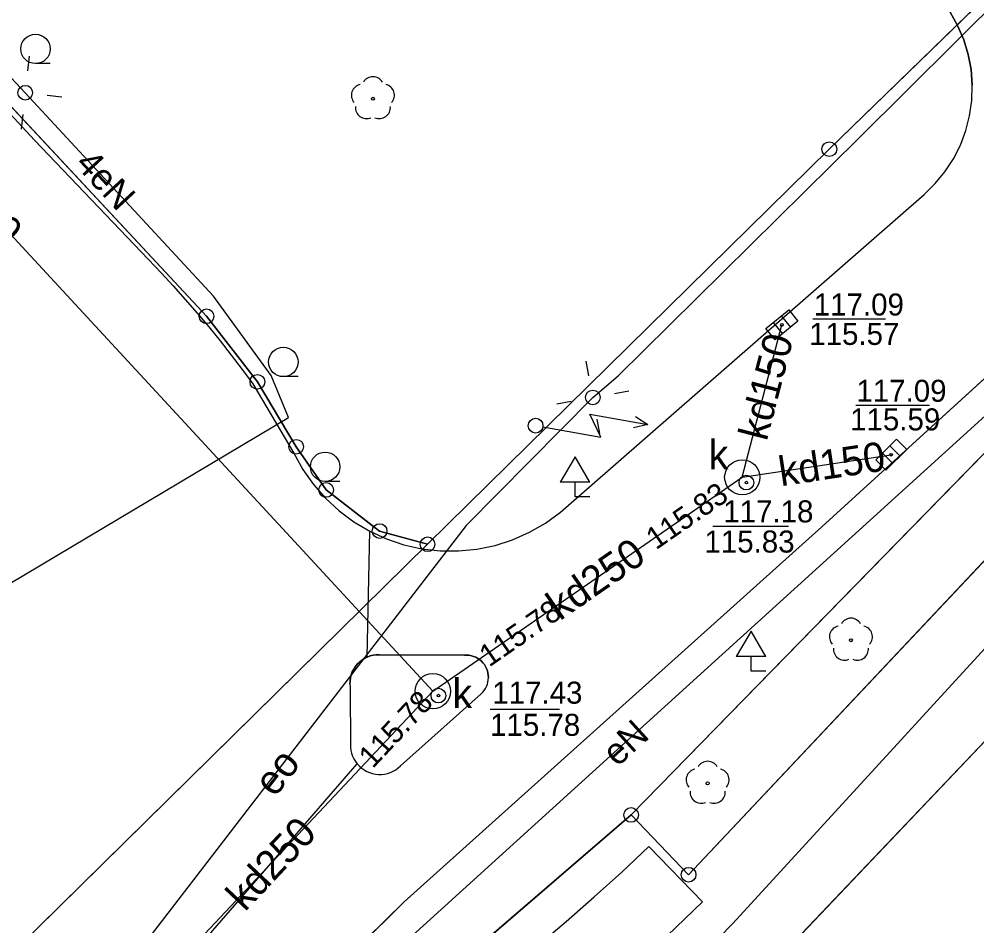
# Model space of a CAD drawing. Extents: x 6434771 to 6436222, y 5663454 to 5664782.
# Drawn here: x 6435500.32 to 6435532.91, y 5663768.81 to 5663799.67 of the extents above; entities that cross this region are included whole.
import ezdxf

# ---------------------------------------------------------------- set-up
doc = ezdxf.new("R2010")
doc.units = 0
for name, color, linetype in [('Warstwa 1', 7, 'Continuous'), ('Warstwa 10', 7, 'Continuous'), ('Warstwa 11', 7, 'Continuous'), ('Warstwa 12', 7, 'Continuous'), ('Warstwa 13', 7, 'Continuous'), ('Warstwa 14', 7, 'Continuous'), ('Warstwa 15', 7, 'Continuous'), ('Warstwa 2', 7, 'Continuous'), ('Warstwa 31', 7, 'Continuous'), ('Warstwa 37', 7, 'Continuous'), ('Warstwa 4', 7, 'Continuous'), ('Warstwa 40', 7, 'Continuous'), ('Warstwa 5', 7, 'Continuous'), ('Warstwa 6', 7, 'Continuous'), ('Warstwa 7', 7, 'Continuous'), ('Warstwa 8', 7, 'Continuous'), ('Warstwa 9', 7, 'Continuous')]:
    doc.layers.add(name, color=color, linetype=linetype)

msp = doc.modelspace()

# ---------------------------------------------------------------- linework, layer by layer
at = {"layer": 'Warstwa 1'}
for p, q in [((6435527.892, 5663795.248), (6435570.992, 5663837.121)), ((6435527.892, 5663795.248), (6435570.992, 5663837.121)), ((6435521.147, 5663772.588), (6435548.671, 5663800.788)), ((6435521.147, 5663772.588), (6435548.671, 5663800.788)), ((6435497.48, 5663799.45), (6435506.7, 5663789.56)), ((6435497.48, 5663799.45), (6435506.7, 5663789.56)), ((6435514.22, 5663781.8), (6435527.892, 5663795.248)), ((6435514.22, 5663781.8), (6435527.892, 5663795.248)), ((6435523.103, 5663770.554), (6435543.163, 5663791.864)), ((6435523.103, 5663770.554), (6435543.163, 5663791.864)), ((6435506.7, 5663789.56), (6435508.43, 5663787.33)), ((6435506.7, 5663789.56), (6435508.43, 5663787.33)), ((6435526.058, 5663767.608), (6435546.338, 5663788.935)), ((6435526.058, 5663767.608), (6435546.338, 5663788.935)), ((6435508.43, 5663787.33), (6435509.75, 5663785.12)), ((6435508.43, 5663787.33), (6435509.75, 5663785.12)), ((6435509.75, 5663785.12), (6435510.77, 5663783.65)), ((6435509.75, 5663785.12), (6435510.77, 5663783.65)), ((6435510.77, 5663783.65), (6435512.59, 5663782.25)), ((6435510.77, 5663783.65), (6435512.59, 5663782.25)), ((6435512.59, 5663782.25), (6435514.22, 5663781.8)), ((6435512.59, 5663782.25), (6435514.22, 5663781.8)), ((6435492.76, 5663760.678), (6435514.22, 5663781.8)), ((6435492.76, 5663760.678), (6435514.22, 5663781.8)), ((6435509.313, 5663762.399), (6435521.147, 5663772.588)), ((6435509.313, 5663762.399), (6435521.147, 5663772.588)), ((6435521.147, 5663772.588), (6435523.103, 5663770.554)), ((6435521.147, 5663772.588), (6435523.103, 5663770.554))]:
    msp.add_line(p, q, dxfattribs=at)
msp.add_circle((6435517.897, 5663785.838), 0.25, dxfattribs=at)
at = {"layer": 'Warstwa 10'}
for centre in [(6435527.892, 5663795.248), (6435506.7, 5663789.56), (6435508.43, 5663787.33), (6435509.75, 5663785.12), (6435510.77, 5663783.65), (6435512.59, 5663782.25), (6435514.22, 5663781.8), (6435521.147, 5663772.588), (6435523.103, 5663770.554)]:
    msp.add_circle(centre, 0.25, dxfattribs=at)
at = {"layer": 'Warstwa 11'}
for centre in [(6435512.361, 5663796.966), (6435528.628, 5663778.535), (6435523.752, 5663773.664)]:
    msp.add_circle(centre, 0.05, dxfattribs=at)
for centre, start, end in [((6435512.361, 5663797.341), 30.1471, 149.8529), ((6435512.004, 5663797.082), 102.1471, 221.8529), ((6435512.718, 5663797.082), 318.1471, 77.8529), ((6435512.141, 5663796.663), 174.1471, 293.8529), ((6435512.581, 5663796.663), 246.1471, 5.8529), ((6435528.628, 5663778.91), 30.1471, 149.8529), ((6435528.271, 5663778.651), 102.1471, 221.8529), ((6435528.985, 5663778.651), 318.1471, 77.8529), ((6435528.408, 5663778.232), 174.1471, 293.8529), ((6435528.848, 5663778.232), 246.1471, 5.8529), ((6435523.395, 5663773.78), 102.1471, 221.8529), ((6435523.752, 5663774.039), 30.1471, 149.8529), ((6435524.109, 5663773.78), 318.1471, 77.8529), ((6435523.532, 5663773.361), 174.1471, 293.8529), ((6435523.972, 5663773.361), 246.1471, 5.8529)]:
    msp.add_arc(centre, 0.375, start, end, dxfattribs=at)
at = {"layer": 'Warstwa 12'}
for points in [[(6435497.61, 5663776.71), (6435497.62, 5663777.21), (6435497.63, 5663777.61), (6435498.65, 5663778.12), (6435498.93, 5663779.83), (6435509.49, 5663786.12), (6435508.9, 5663787.55), (6435506.94, 5663790.25), (6435500.53, 5663797.17), (6435496.25, 5663801.75), (6435493.32, 5663804.59), (6435490.84, 5663808.57), (6435490.34, 5663810.94), (6435482.363, 5663815.454)], [(6435519.85, 5663786.8), (6435520.711, 5663787.533), (6435522.45, 5663789.259), (6435528.881, 5663795.616), (6435533.856, 5663800.554)], [(6435506.84, 5663759.48), (6435507.02, 5663760.06), (6435509.66, 5663764.81), (6435538.22, 5663790.73)], [(6435519.85, 5663786.8), (6435515.54, 5663782.44), (6435503.04, 5663766.2), (6435502.06, 5663764.42), (6435502.22, 5663763.12), (6435502.29, 5663762.51), (6435501.16, 5663760.21), (6435500.55, 5663759.21), (6435505.86, 5663755.16), (6435506.73, 5663754.16), (6435505.81, 5663752.14)]]:
    msp.add_lwpolyline(points, dxfattribs=at)
at = {"layer": 'Warstwa 14'}
for p, q in [((6435529.808, 5663789.467), (6435527.334, 5663789.467)), ((6435531.303, 5663786.53), (6435528.793, 5663786.53)), ((6435526.498, 5663782.411), (6435523.929, 5663782.411)), ((6435518.715, 5663776.174), (6435516.347, 5663776.174))]:
    msp.add_line(p, q, dxfattribs=at)
for centre in [(6435526.28, 5663789.27), (6435530, 5663784.85), (6435525.07, 5663783.9), (6435525.07, 5663783.9), (6435514.59, 5663776.65), (6435514.59, 5663776.65), (6435514.59, 5663776.65)]:
    msp.add_circle(centre, 0.045, dxfattribs=at)
at = {"layer": 'Warstwa 15'}
for centre in [(6435524.93, 5663784.08), (6435514.4, 5663776.8)]:
    msp.add_circle(centre, 0.6, dxfattribs=at)
at = {"layer": 'Warstwa 2'}
for centre in [(6435500.53, 5663797.17), (6435519.845, 5663786.799)]:
    msp.add_circle(centre, 0.25, dxfattribs=at)
at = {"layer": 'Warstwa 31'}
for p, q in [((6435519.738, 5663783.911), (6435519.238, 5663784.777)), ((6435519.238, 5663783.411), (6435519.238, 5663783.911)), ((6435519.738, 5663783.411), (6435519.238, 5663783.411)), ((6435525.727, 5663777.979), (6435525.227, 5663778.845)), ((6435525.227, 5663777.479), (6435525.227, 5663777.979)), ((6435525.727, 5663777.479), (6435525.227, 5663777.479))]:
    msp.add_line(p, q, dxfattribs=at)
for points in [[(6435519.238, 5663784.777), (6435518.738, 5663783.911)], [(6435519.738, 5663783.911), (6435518.738, 5663783.911)], [(6435525.227, 5663778.845), (6435524.727, 5663777.979)], [(6435525.727, 5663777.979), (6435524.727, 5663777.979)]]:
    msp.add_lwpolyline(points, dxfattribs=at)
at = {"layer": 'Warstwa 37'}
for points in [[(6435536.411, 5663781.778), (6435524.604, 5663768.893)], [(6435524.604, 5663768.893), (6435523.66, 5663767.922), (6435522.692, 5663766.975), (6435521.701, 5663766.052), (6435520.687, 5663765.154), (6435519.652, 5663764.282), (6435518.595, 5663763.435), (6435517.517, 5663762.615), (6435516.419, 5663761.822), (6435515.302, 5663761.056)]]:
    msp.add_lwpolyline(points, dxfattribs=at)
at = {"layer": 'Warstwa 4'}
for p, q in [((6435526.257, 5663789.574), (6435526.574, 5663789.187)), ((6435525.986, 5663789.353), (6435526.303, 5663788.966)), ((6435529.7, 5663784.905), (6435530.051, 5663784.549)), ((6435529.949, 5663785.151), (6435530.3, 5663784.795))]:
    msp.add_line(p, q, dxfattribs=at)
for points in [[(6435500.615, 5663797.915), (6435500.671, 5663798.412)], [(6435501.275, 5663797.085), (6435501.772, 5663797.029)], [(6435500.445, 5663796.425), (6435500.389, 5663795.928)], [(6435519.71, 5663787.537), (6435519.619, 5663788.028)], [(6435520.583, 5663786.934), (6435521.074, 5663787.025)], [(6435519.107, 5663786.664), (6435518.616, 5663786.573)], [(6435519.98, 5663786.061), (6435520.071, 5663785.57)]]:
    msp.add_lwpolyline(points, dxfattribs=at)
for points in [[(6435525.735, 5663789.147), (6435526.509, 5663789.78), (6435526.825, 5663789.393), (6435526.051, 5663788.76)], [(6435529.469, 5663784.676), (6435530.18, 5663785.379), (6435530.531, 5663785.024), (6435529.82, 5663784.321)]]:
    msp.add_lwpolyline(points, close=True, dxfattribs=at)
for centre in [(6435525.07, 5663783.9), (6435514.59, 5663776.65)]:
    msp.add_circle(centre, 0.25, dxfattribs=at)
at = {"layer": 'Warstwa 40'}
msp.add_line((6435518.143, 5663785.795), (6435520.113, 5663785.451), dxfattribs=at)
for points in [[(6435518.143, 5663785.795), (6435520.113, 5663785.451), (6435519.741, 5663786.227), (6435521.712, 5663785.883)], [(6435521.292, 5663786.155), (6435521.712, 5663785.883), (6435521.225, 5663785.769)]]:
    msp.add_lwpolyline(points, dxfattribs=at)
msp.add_circle((6435517.897, 5663785.838), 0.25, dxfattribs=at)
at = {"layer": 'Warstwa 6'}
for p, q in [((6435501.38, 5663798.16), (6435500.88, 5663798.16)), ((6435509.813, 5663787.506), (6435509.313, 5663787.506)), ((6435511.236, 5663783.938), (6435510.736, 5663783.938))]:
    msp.add_line(p, q, dxfattribs=at)
for points in [[(6435497.48, 5663799.45), (6435506.7, 5663789.56), (6435508.43, 5663787.33), (6435509.75, 5663785.12), (6435510.77, 5663783.65), (6435512.59, 5663782.25), (6435514.22, 5663781.8), (6435527.892, 5663795.248), (6435570.992, 5663837.121), (6435586.939, 5663852.54), (6435599.429, 5663860.81), (6435608.979, 5663864.176), (6435617.268, 5663864.926), (6435627.619, 5663865.031), (6435640.832, 5663867.732), (6435649.164, 5663870.462), (6435662.228, 5663877.475)], [(6435570.992, 5663837.121), (6435527.892, 5663795.248), (6435514.22, 5663781.8), (6435492.76, 5663760.678), (6435502.002, 5663754.167), (6435504.911, 5663757.372), (6435509.313, 5663762.399), (6435521.147, 5663772.588), (6435548.671, 5663800.788)], [(6435548.671, 5663800.788), (6435521.147, 5663772.588), (6435523.103, 5663770.554), (6435543.163, 5663791.864), (6435547.892, 5663795.057), (6435552.721, 5663796.629), (6435556.818, 5663797.2), (6435563.282, 5663796.602), (6435571.928, 5663792.927), (6435578.259, 5663786.341), (6435582.013, 5663777.505), (6435581.903, 5663767.556), (6435577.311, 5663758.31), (6435571.527, 5663753.09), (6435533.459, 5663736.247), (6435548.335, 5663741.528), (6435569.265, 5663749.587), (6435586.612, 5663753.338), (6435592.395, 5663758.549), (6435606.056, 5663770.975), (6435613.539, 5663781.965), (6435615.412, 5663784.713), (6435621.643, 5663793.868), (6435632.116, 5663809.073)], [(6435547.198, 5663801.229), (6435542.95, 5663796.915), (6435539.74, 5663793.64), (6435534.45, 5663788.61), (6435527.64, 5663782.4), (6435513.43, 5663769.63), (6435509.63, 5663765.9)], [(6435531.12, 5663793.71), (6435531.495, 5663794.077), (6435531.828, 5663794.482), (6435532.114, 5663794.921), (6435532.351, 5663795.389), (6435532.536, 5663795.88), (6435532.666, 5663796.388), (6435532.739, 5663796.907), (6435532.756, 5663797.432), (6435532.715, 5663797.955), (6435532.618, 5663798.47), (6435532.465, 5663798.972), (6435532.258, 5663799.453), (6435532, 5663799.91)], [(6435492.76, 5663760.678), (6435514.22, 5663781.8), (6435512.59, 5663782.25), (6435510.77, 5663783.65), (6435509.75, 5663785.12), (6435508.43, 5663787.33), (6435506.7, 5663789.56), (6435497.48, 5663799.45)], [(6435497.34, 5663799.33), (6435500.85, 5663795.55), (6435504.73, 5663791.49), (6435505.152, 5663791.044), (6435505.568, 5663790.592), (6435505.977, 5663790.134), (6435506.379, 5663789.67), (6435506.774, 5663789.2), (6435507.161, 5663788.723), (6435507.541, 5663788.241), (6435507.914, 5663787.753), (6435508.28, 5663787.26), (6435509.67, 5663784.9), (6435509.974, 5663784.352), (6435510.335, 5663783.838), (6435510.748, 5663783.366), (6435511.208, 5663782.94), (6435511.711, 5663782.565), (6435512.251, 5663782.245), (6435512.821, 5663781.983), (6435513.416, 5663781.784), (6435514.028, 5663781.648), (6435514.652, 5663781.578), (6435515.279, 5663781.573), (6435515.903, 5663781.636), (6435516.517, 5663781.763), (6435517.115, 5663781.955), (6435517.689, 5663782.209), (6435518.232, 5663782.522), (6435518.74, 5663782.89), (6435531.12, 5663793.71)], [(6435552.721, 5663796.629), (6435547.892, 5663795.057), (6435543.163, 5663791.864), (6435523.103, 5663770.554), (6435521.147, 5663772.588), (6435509.313, 5663762.399), (6435504.911, 5663757.372), (6435502.002, 5663754.167), (6435506.094, 5663751.807), (6435526.058, 5663767.608), (6435546.338, 5663788.935), (6435550.407, 5663791.326)], [(6435511.59, 5663776.94), (6435511.6, 5663774.89), (6435511.613, 5663774.788), (6435511.637, 5663774.687), (6435511.671, 5663774.589), (6435511.715, 5663774.496), (6435511.768, 5663774.407), (6435511.831, 5663774.325), (6435511.901, 5663774.249), (6435511.979, 5663774.181), (6435512.063, 5663774.122), (6435512.153, 5663774.072), (6435512.248, 5663774.031), (6435512.347, 5663774), (6435512.448, 5663773.979), (6435512.551, 5663773.969), (6435512.654, 5663773.97), (6435512.757, 5663773.982), (6435512.858, 5663774.004), (6435512.956, 5663774.036), (6435513.05, 5663774.078), (6435513.14, 5663774.13), (6435513.223, 5663774.191), (6435513.3, 5663774.26), (6435516.05, 5663776.71), (6435516.104, 5663776.766), (6435516.152, 5663776.827), (6435516.194, 5663776.893), (6435516.229, 5663776.963), (6435516.256, 5663777.036), (6435516.276, 5663777.112), (6435516.288, 5663777.189), (6435516.292, 5663777.267), (6435516.288, 5663777.345), (6435516.277, 5663777.422), (6435516.257, 5663777.498), (6435516.23, 5663777.571), (6435516.195, 5663777.641), (6435516.154, 5663777.707), (6435516.106, 5663777.768), (6435516.052, 5663777.824), (6435515.992, 5663777.875), (6435515.928, 5663777.919), (6435515.859, 5663777.956), (6435515.787, 5663777.987), (6435515.712, 5663778.009), (6435515.636, 5663778.024), (6435515.558, 5663778.031), (6435515.48, 5663778.03), (6435512.58, 5663778.04), (6435512.475, 5663778.038), (6435512.371, 5663778.024), (6435512.268, 5663777.999), (6435512.17, 5663777.963), (6435512.075, 5663777.916), (6435511.986, 5663777.86), (6435511.904, 5663777.794), (6435511.83, 5663777.72), (6435511.764, 5663777.638), (6435511.707, 5663777.549), (6435511.66, 5663777.455), (6435511.624, 5663777.356), (6435511.598, 5663777.254), (6435511.584, 5663777.15), (6435511.581, 5663777.045), (6435511.59, 5663776.94)]]:
    msp.add_lwpolyline(points, dxfattribs=at)
msp.add_lwpolyline([(6435557.506, 5663792.861), (6435553.992, 5663792.563), (6435550.407, 5663791.326), (6435546.338, 5663788.935), (6435526.058, 5663767.608), (6435506.094, 5663751.807), (6435529.689, 5663738.733), (6435568.207, 5663755.62), (6435573.888, 5663760.552), (6435577.803, 5663768.465), (6435578.155, 5663776.031), (6435574.677, 5663783.684), (6435569.533, 5663789.156), (6435561.733, 5663792.55)], close=True, dxfattribs=at)
for centre, radius in [((6435500.88, 5663798.66), 0.5), ((6435526.28, 5663789.27), 0.045), ((6435509.313, 5663788.006), 0.5), ((6435510.736, 5663784.438), 0.5), ((6435530, 5663784.85), 0.045), ((6435525.07, 5663783.9), 0.045), ((6435514.59, 5663776.65), 0.045)]:
    msp.add_circle(centre, radius, dxfattribs=at)
at = {"layer": 'Warstwa 7'}
for points in [[(6435482.98, 5663810.8), (6435514.4, 5663776.8)], [(6435524.93, 5663784.08), (6435526.28, 5663789.27)], [(6435524.93, 5663784.08), (6435530, 5663784.85)], [(6435514.4, 5663776.8), (6435524.93, 5663784.08)], [(6435514.4, 5663776.8), (6435502.93, 5663764.6)]]:
    msp.add_lwpolyline(points, dxfattribs=at)
at = {"layer": 'Warstwa 8'}
for p, q in [((6435532, 5663799.91), (6435532.258, 5663799.453)), ((6435497.357, 5663799.312), (6435500.85, 5663795.55)), ((6435532.258, 5663799.453), (6435532.465, 5663798.972)), ((6435532.465, 5663798.972), (6435532.618, 5663798.47)), ((6435532.618, 5663798.47), (6435532.715, 5663797.955)), ((6435532.715, 5663797.955), (6435532.756, 5663797.432)), ((6435532.739, 5663796.907), (6435532.756, 5663797.432)), ((6435532.666, 5663796.388), (6435532.739, 5663796.907)), ((6435532.536, 5663795.88), (6435532.666, 5663796.388)), ((6435532.351, 5663795.389), (6435532.536, 5663795.88)), ((6435500.85, 5663795.55), (6435504.73, 5663791.49)), ((6435532.114, 5663794.921), (6435532.351, 5663795.389)), ((6435531.828, 5663794.482), (6435532.114, 5663794.921)), ((6435531.495, 5663794.077), (6435531.828, 5663794.482)), ((6435531.12, 5663793.71), (6435531.495, 5663794.077)), ((6435518.74, 5663782.89), (6435531.12, 5663793.71)), ((6435504.73, 5663791.49), (6435505.152, 5663791.044)), ((6435505.152, 5663791.044), (6435505.568, 5663790.592)), ((6435505.568, 5663790.592), (6435505.977, 5663790.134)), ((6435505.977, 5663790.134), (6435506.379, 5663789.67)), ((6435506.379, 5663789.67), (6435506.774, 5663789.2)), ((6435506.774, 5663789.2), (6435507.161, 5663788.723)), ((6435507.161, 5663788.723), (6435507.541, 5663788.241)), ((6435527.64, 5663782.4), (6435534.45, 5663788.61)), ((6435507.541, 5663788.241), (6435507.914, 5663787.753)), ((6435507.914, 5663787.753), (6435508.28, 5663787.26)), ((6435508.28, 5663787.26), (6435509.67, 5663784.9)), ((6435509.67, 5663784.9), (6435509.974, 5663784.352)), ((6435509.974, 5663784.352), (6435510.335, 5663783.838)), ((6435510.335, 5663783.838), (6435510.748, 5663783.366)), ((6435510.748, 5663783.366), (6435511.208, 5663782.94)), ((6435511.208, 5663782.94), (6435511.711, 5663782.565)), ((6435518.232, 5663782.522), (6435518.74, 5663782.89)), ((6435511.711, 5663782.565), (6435512.251, 5663782.245)), ((6435513.43, 5663769.63), (6435527.64, 5663782.4)), ((6435517.689, 5663782.209), (6435518.232, 5663782.522)), ((6435512.17, 5663777.963), (6435512.251, 5663782.245)), ((6435512.17, 5663777.963), (6435512.251, 5663782.245)), ((6435512.251, 5663782.245), (6435512.821, 5663781.983)), ((6435512.821, 5663781.983), (6435513.416, 5663781.784)), ((6435517.115, 5663781.955), (6435517.689, 5663782.209)), ((6435513.416, 5663781.784), (6435514.028, 5663781.648)), ((6435514.028, 5663781.648), (6435514.652, 5663781.578)), ((6435515.279, 5663781.573), (6435515.903, 5663781.636)), ((6435515.903, 5663781.636), (6435516.517, 5663781.763)), ((6435516.517, 5663781.763), (6435517.115, 5663781.955)), ((6435514.652, 5663781.578), (6435515.279, 5663781.573)), ((6435511.83, 5663777.72), (6435511.904, 5663777.794)), ((6435511.904, 5663777.794), (6435511.986, 5663777.86)), ((6435511.986, 5663777.86), (6435512.075, 5663777.916)), ((6435512.075, 5663777.916), (6435512.17, 5663777.963)), ((6435512.17, 5663777.963), (6435512.268, 5663777.999)), ((6435512.268, 5663777.999), (6435512.371, 5663778.024)), ((6435512.371, 5663778.024), (6435512.475, 5663778.038)), ((6435512.475, 5663778.038), (6435512.58, 5663778.04)), ((6435512.58, 5663778.04), (6435515.48, 5663778.03)), ((6435515.48, 5663778.03), (6435515.558, 5663778.031)), ((6435515.558, 5663778.031), (6435515.636, 5663778.024)), ((6435515.636, 5663778.024), (6435515.712, 5663778.009)), ((6435515.712, 5663778.009), (6435515.787, 5663777.987)), ((6435515.787, 5663777.987), (6435515.859, 5663777.956)), ((6435515.859, 5663777.956), (6435515.928, 5663777.919)), ((6435515.928, 5663777.919), (6435515.992, 5663777.875)), ((6435515.992, 5663777.875), (6435516.052, 5663777.824)), ((6435516.052, 5663777.824), (6435516.106, 5663777.768)), ((6435516.106, 5663777.768), (6435516.154, 5663777.707)), ((6435511.624, 5663777.356), (6435511.66, 5663777.455)), ((6435511.66, 5663777.455), (6435511.707, 5663777.549)), ((6435511.707, 5663777.549), (6435511.764, 5663777.638)), ((6435511.764, 5663777.638), (6435511.83, 5663777.72)), ((6435516.154, 5663777.707), (6435516.195, 5663777.641)), ((6435516.195, 5663777.641), (6435516.23, 5663777.571)), ((6435516.23, 5663777.571), (6435516.257, 5663777.498)), ((6435516.257, 5663777.498), (6435516.277, 5663777.422)), ((6435516.277, 5663777.422), (6435516.288, 5663777.345)), ((6435511.581, 5663777.045), (6435511.584, 5663777.15)), ((6435511.584, 5663777.15), (6435511.598, 5663777.254)), ((6435511.598, 5663777.254), (6435511.624, 5663777.356)), ((6435516.256, 5663777.036), (6435516.276, 5663777.112)), ((6435516.276, 5663777.112), (6435516.288, 5663777.189)), ((6435516.288, 5663777.345), (6435516.292, 5663777.267)), ((6435516.288, 5663777.189), (6435516.292, 5663777.267)), ((6435511.581, 5663777.045), (6435511.59, 5663776.94)), ((6435511.59, 5663776.94), (6435511.6, 5663774.89)), ((6435516.05, 5663776.71), (6435516.104, 5663776.766)), ((6435516.104, 5663776.766), (6435516.152, 5663776.827)), ((6435516.152, 5663776.827), (6435516.194, 5663776.893)), ((6435516.194, 5663776.893), (6435516.229, 5663776.963)), ((6435516.229, 5663776.963), (6435516.256, 5663777.036)), ((6435513.3, 5663774.26), (6435516.05, 5663776.71)), ((6435511.6, 5663774.89), (6435511.613, 5663774.788)), ((6435511.613, 5663774.788), (6435511.637, 5663774.687)), ((6435511.637, 5663774.687), (6435511.671, 5663774.589)), ((6435511.671, 5663774.589), (6435511.715, 5663774.496)), ((6435511.715, 5663774.496), (6435511.768, 5663774.407)), ((6435504.41, 5663765.773), (6435511.831, 5663774.325)), ((6435504.41, 5663765.773), (6435511.831, 5663774.325)), ((6435511.768, 5663774.407), (6435511.831, 5663774.325)), ((6435511.831, 5663774.325), (6435511.901, 5663774.249)), ((6435511.901, 5663774.249), (6435511.979, 5663774.181)), ((6435511.979, 5663774.181), (6435512.063, 5663774.122)), ((6435513.14, 5663774.13), (6435513.223, 5663774.191)), ((6435513.223, 5663774.191), (6435513.3, 5663774.26)), ((6435512.063, 5663774.122), (6435512.153, 5663774.072)), ((6435512.153, 5663774.072), (6435512.248, 5663774.031)), ((6435512.248, 5663774.031), (6435512.347, 5663774)), ((6435512.347, 5663774), (6435512.448, 5663773.979)), ((6435512.448, 5663773.979), (6435512.551, 5663773.969)), ((6435512.551, 5663773.969), (6435512.654, 5663773.97)), ((6435512.654, 5663773.97), (6435512.757, 5663773.982)), ((6435512.757, 5663773.982), (6435512.858, 5663774.004)), ((6435512.858, 5663774.004), (6435512.956, 5663774.036)), ((6435512.956, 5663774.036), (6435513.05, 5663774.078)), ((6435513.05, 5663774.078), (6435513.14, 5663774.13)), ((6435509.63, 5663765.9), (6435513.43, 5663769.63))]:
    msp.add_line(p, q, dxfattribs=at)
at = {"layer": 'Warstwa 9'}
for p, q in [((6435520.827, 5663770.647), (6435521.754, 5663771.51)), ((6435521.754, 5663771.51), (6435523.582, 5663769.628)), ((6435519.888, 5663769.798), (6435520.827, 5663770.647)), ((6435518.937, 5663768.962), (6435519.888, 5663769.798)), ((6435522.378, 5663768.472), (6435523.582, 5663769.628)), ((6435517.974, 5663768.141), (6435518.937, 5663768.962))]:
    msp.add_line(p, q, dxfattribs=at)

# ---------------------------------------------------------------- texts
at = {"layer": 'Warstwa 13'}
for s, height, rotation, p in [('4eN', 0.9, 312.8063, (6435502.192, 5663794.713)), ('eN', 0.9, 42.227, (6435520.679, 5663774.202)), ('eo', 1, 52.4142, (6435509.028, 5663773.161))]:
    msp.add_text(s, height=height, rotation=rotation, dxfattribs=at).set_placement(p)
at = {"layer": 'Warstwa 14'}
for s, p in [('115.57', (6435527.209, 5663788.587)), ('115.59', (6435528.6, 5663785.677)), ('115.83', (6435523.642, 5663781.519)), ('115.78', (6435516.347, 5663775.281))]:
    msp.add_text(s, height=0.75, dxfattribs=at).set_placement(p)
for s, rotation, p in [('115.83', 34.6582, (6435521.991, 5663781.593)), ('115.78', 34.6582, (6435516.316, 5663777.603)), ('115.78', 46.7648, (6435512.352, 5663774.142))]:
    msp.add_text(s, height=0.75, rotation=rotation, dxfattribs=at).set_placement(p)
at = {"layer": 'Warstwa 5'}
for p in [(6435523.782, 5663784.354), (6435515.069, 5663776.226)]:
    msp.add_text('k', height=1, dxfattribs=at).set_placement(p)
at = {"layer": 'Warstwa 6'}
for s, p in [('117.09', (6435527.363, 5663789.587)), ('117.09', (6435528.813, 5663786.65)), ('117.18', (6435524.283, 5663782.546)), ('117.43', (6435516.423, 5663776.376))]:
    msp.add_text(s, height=0.75, dxfattribs=at).set_placement(p)
at = {"layer": 'Warstwa 7'}
for s, rotation, p in [('kd250', 312.7433, (6435497.309, 5663794.558)), ('kd150', 75.4184, (6435525.76, 5663785.283)), ('kd150', 8.6345, (6435526.247, 5663783.774)), ('kd250', 34.6582, (6435518.72, 5663779.179)), ('kd250', 46.7648, (6435508.006, 5663769.269))]:
    msp.add_text(s, height=1, rotation=rotation, dxfattribs=at).set_placement(p)

doc.saveas('drawing.dxf')
